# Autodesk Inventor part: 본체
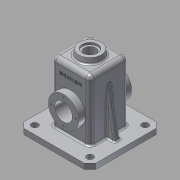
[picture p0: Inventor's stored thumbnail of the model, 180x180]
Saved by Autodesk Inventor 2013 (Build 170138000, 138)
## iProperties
Created: 2016-02
Part Number: 본체
Material: 알루미늄 6061
Document SubType Name: Modeling
Designer: user-11
Density: 2.71 g/cm^3
Mass: 939.134 g
Surface Area: 1045.46 cm^2
Volume: 346.544 cm^3
Author: user-11
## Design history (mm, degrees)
sketch "스케치1"
  geometry: L1 (-65, 65)-(65, 65); L2 (65, 65)-(65, -65); L3 (65, -65)-(-65, -65); L4 (-65, -65)-(-65, 65); 1 further point
  constraints: 8 end point, 2 parallel, 1 horizontal, 1 perpendicular
  dimensions: "d0" = 130 distance between parallel lines of L2 L4; "d3" = 130 distance between parallel lines of L3 L1; "d4" = 65 distance from line of point (0, 0) L1; "d5" = 65 distance from line of point (0, 0) L4
extrude "돌출1" new body sketch "스케치1" distance "d6" = 10; taper "d7" = 0 deg
chamfer "모따기1" distance "d8" = 10; stored, may be unused: second distance "d9" = 2, angle "d10" = 45 deg
sketch "스케치2"
  geometry: L1 (-65, 55)-(-65, -55) reference; L2 (-55, -65)-(55, -65) reference; L3 (65, -55)-(65, 55) reference; L4 (55, 65)-(-55, 65) reference; C1 r 6 at (-50, 50); C2 r 6 at (50, 50); C3 r 6 at (50, -50); C4 r 6 at (-50, -50); 1 further point
  constraints: 4 centre point
  dimensions: "d11" = 15 distance from line of L1 C1.centre; "d12" = 15 distance from line of L4 C1.centre; "d13" = 15 distance from line of L4 C2.centre; "d14" = 15 distance from line of L3 C2.centre; "d15" = 15 distance from line of L3 C3.centre; "d16" = 15 distance from line of L2 C3.centre; "d17" = 15 distance from line of L2 C4.centre; "d18" = 15 distance from line of L1 C4.centre; "d19" = 12 diameter of C1; "d20" = 12 diameter of C2; "d21" = 12 diameter of C3; "d22" = 12 diameter of C4
extrude "돌출2" cut sketch "스케치2" distance "d23" = 10; taper "d24" = 0 deg
sketch "스케치3"
  geometry: L1 (-35, 35)-(35, 35); L2 (35, 35)-(35, -35); L3 (35, -35)-(-35, -35); L4 (-35, -35)-(-35, 35); 1 further point
  constraints: 8 end point, 2 parallel, 1 horizontal, 1 perpendicular
  dimensions: "d25" = 70 distance between parallel lines of L2 L4; "d27" = 70 distance between parallel lines of L3 L1; "d28" = 35 distance from line of point (0, 0) L1; "d29" = 35 distance from line of point (0, 0) L4
extrude "돌출3" join sketch "스케치3" distance "d30" = 110; taper "d31" = 0 deg
feature "쉘1" dims "d32" = 5
sketch "스케치4"
  geometry: L1 (15.417, -30)-(15.417, -90) reference; L2 (75.417, -30)-(15.417, -30) reference; L3 (75.417, -90)-(75.417, -30) reference; L4 (15.417, -90)-(75.417, -90) reference; L5 (105.417, -14.583)-(105.417, -105.417) reference; L6 (0, 0)-(90.835, 0) reference; L7 (-14.583, -105.417)-(-14.583, -14.583) reference; L8 (90.835, -120)-(0, -120) reference; A1 r 11 centre (95.417, -110) between (105.417, -105.417) and (90.835, -120) reference; A2 r 11 centre (95.417, -10) between (90.835, 0) and (105.417, -14.583) reference; A3 r 11 centre (-4.583, -10) between (-14.583, -14.583) and (0, 0) reference; A4 r 11 centre (-4.583, -110) between (0, -120) and (-14.583, -105.417) reference; 1 further point
extrude "돌출4" join sketch "스케치4" distance "d33" = 5; taper "d34" = 0 deg
fillet "모깎기1" dims "d35" = 8, "d36" = 3
node "작업 평면1"
sketch "스케치5"
  geometry: C1 r 20 at (0, 0); 1 further point
  constraints: 1 centre point, 1 coincident
  dimensions: "d38" = 40 diameter of C1
extrude "돌출5" join sketch "스케치5" stored distance "d40" = 5; taper "d41" = 10 deg
sketch "스케치6"
  geometry: C1 r 20 at (0, 0) reference; C2 r 14 at (0, 0)
  constraints: 1 centre point, 1 coincident
  dimensions: "d42" = 28 diameter of C2
extrude "돌출6" cut sketch "스케치6" distance "d44" = 4; taper "d45" = 0 deg
sketch "스케치7"
  geometry: C1 r 14 at (0, 0) reference; C2 r 10.5 at (0, 0)
  constraints: 1 centre point, 1 coincident
  dimensions: "d46" = 21 diameter of C2
extrude "돌출7" cut sketch "스케치7" stored distance "d48" = 4; taper "d49" = 0 deg
sketch "스케치8"
  geometry: C1 r 27.5 at (27, 45); 1 further point
  constraints: 1 centre point
  dimensions: "d50" = 55 diameter of C1; "d52" = 0 horizontal distance of point (27, -10) C1.centre; "d53" = 55 distance of point (27, -10) C1.centre
extrude "돌출8" join sketch "스케치8" distance "d54" = 13; taper "d55" = 0 deg
sketch "스케치9"
  geometry: C1 r 27.5 at (27, -55); 1 further point
  constraints: 1 centre point
  dimensions: "d56" = 55 diameter of C1; "d58" = 0 horizontal distance of point (27, 0) C1.centre; "d59" = 55 distance of point (27, 0) C1.centre
extrude "돌출9" join sketch "스케치9" distance "d60" = 7; taper "d61" = -45 deg
sketch "스케치10"
  geometry: C1 r 27.5 at (0, 0) reference; C2 r 16 at (0, 0); 1 further point
  constraints: 1 centre point, 1 coincident
  dimensions: "d62" = 32 diameter of C2
extrude "돌출10" cut sketch "스케치10" stored distance "d64" = 7; taper "d65" = 0 deg
sketch "스케치11"
  geometry: C1 r 16 at (0, 0) reference; C2 r 2 at (0, 22.5); 1 further point
  constraints: 1 centre point
  dimensions: "d66" = 4 diameter of C2; "d68" = 0 horizontal distance of C1.centre C2.centre; "d69" = 22.5 distance of C1.centre C2.centre
hole "구멍1" sketch "스케치11" at (0, 22.5) diameter "d70" = 3.242; stored, may be unused: countersink angle "d74" = 90 deg, drill point angle "d76" = 118 deg; dims "d71" = 8, "d72" = 4, "d73" = 2, "d75" = 10
sketch "스케치12"
  geometry: L1 (-35, 10)-(-35, 112) reference; L2 (55, 10)-(-55, 10) reference; L3 (-65, 10)-(-55, 10) reference; L4 (-35, 95.069)-(-50, 10); L5 (-65, 0)-(-65, 10) reference; 1 further point
  constraints: 2 end point, 2 point on line
  dimensions: "d80" = 15 distance from line of L5 L4.end; "d82" = 10 deg angle of L4 L5
feature "리브1" sketch "스케치12" dims "d83" = 1, "d84" = 10, "d85" = 0, "d86" = 0, "d87" = 1, "d88" = 1
sketch "스케치13"
  geometry: L1 (5.471, -8.998)-(48.529, -8.998); L2 (48.529, -8.998)-(48.529, -15.002); L3 (48.529, -15.002)-(5.471, -15.002); L4 (5.471, -15.002)-(5.471, -8.998); L5 (5.471, -12)-(48.529, -12); L6 (27, -8.998)-(27, -15.002); L7 (7, 18)-(47, 18) reference; L8 (62, -102)-(62, 0) reference; 1 further point
  constraints: 4 end point, 4 midpoint, 2 other
  dimensions: "d89" = 30 distance between parallel lines of L5 L7; "d90" = 35 distance between parallel lines of L8 L6
extrude "돌출11" join sketch "스케치13" distance "d91" = 0.5; taper "d92" = 0 deg
fillet "모깎기2" dims "d93" = 0.5, "d94" = 3
fillet "모깎기3" dims "d95" = 3
node "솔리드1"
pattern_circular "원형 패턴1" dims angle "d78" = 360 deg
mirror "대칭1"
mirror "대칭2"
